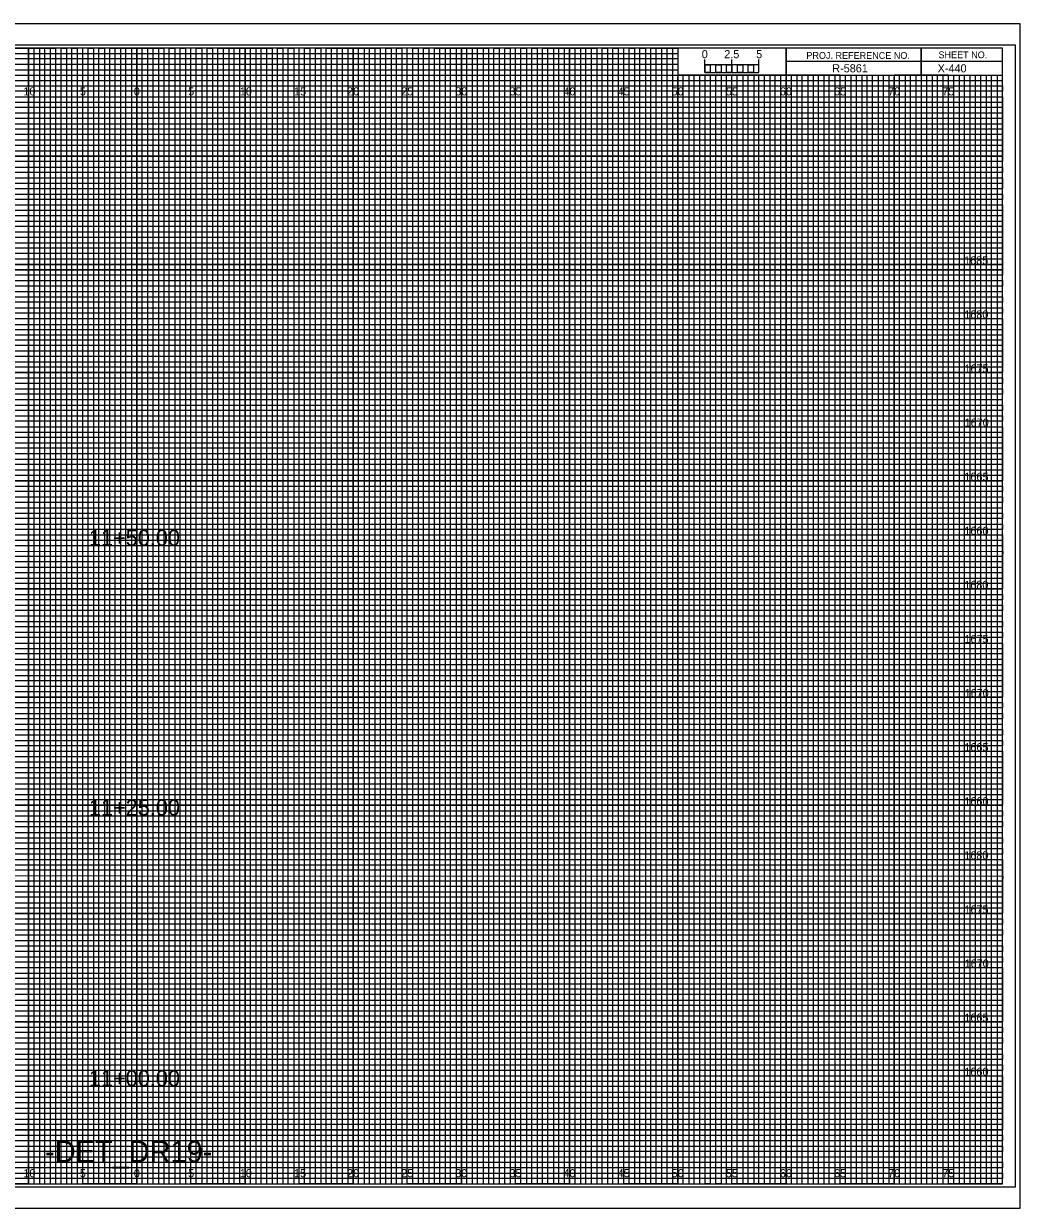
# Model space of a CAD drawing. Extents: x -7 to 162, y -2 to 327.
# Drawn here: x 69.5 to 161.7, y 217.7 to 327.2 of the extents above; entities that cross this region are included whole.
import ezdxf

# ---------------------------------------------------------------- set-up
doc = ezdxf.new("R2010")
doc.units = 0
for name, color, linetype in [('Prop Horizontal Alignment', 7, 'Continuous'), ('Prop XS Alignment Label', 7, 'Continuous'), ('Prop XS Bar Scale Labels', 7, 'Continuous'), ('Prop XS Project Number', 7, 'Continuous'), ('Prop XS Sheet Number', 7, 'Continuous'), ('Raster_Level_0', 7, 'Continuous'), ('Scratch_Level_3', 7, 'Continuous'), ('Sheet Cross Section CELL', 7, 'Continuous'), ('Sheet Cross Section Grid Major CELL', 7, 'Continuous'), ('Sheet Cross Section Grid Middle CELL', 7, 'Continuous'), ('Sheet Cross Section Grid Minor 1 CELL', 7, 'Continuous'), ('Sheet Cross Section Grid Minor 2 CELL', 7, 'Continuous'), ('Sheet Cross Section Scale CELL', 7, 'Continuous'), ('Sheet Cutting Line CELL', 7, 'Continuous'), ('Sheet DOT Grid CELL', 7, 'Continuous'), ('Sheet Plot Border Inside CELL', 7, 'Continuous'), ('Sheet Plot Border Outside CELL', 7, 'Continuous')]:
    doc.layers.add(name, color=color, linetype=linetype)

msp = doc.modelspace()

# ---------------------------------------------------------------- linework, layer by layer
at = {"layer": 'Sheet Cross Section CELL'}
for p, q in [((152.5, 325), (152.5, 322.5)), ((152.5, 322.5), (152.5, 325)), ((160, 323.75), (140, 323.75)), ((140, 323.75), (140, 322.5)), ((140, 322.5), (160, 322.5))]:
    msp.add_line(p, q, dxfattribs=at)
for points in [[(160, 325), (0, 325), (0, 220), (160, 220)], [(140, 325), (130, 325), (130, 322.51), (140, 322.51)], [(160, 325), (140, 325), (140, 322.5), (160, 322.5)]]:
    msp.add_lwpolyline(points, close=True, dxfattribs=at)
at = {"layer": 'Sheet Cross Section Grid Major CELL'}
for p, q in [((75, 325), (70, 325)), ((70, 325), (70, 220)), ((75, 220), (75, 325)), ((85, 325), (80, 325)), ((80, 325), (80, 220)), ((85, 220), (85, 325)), ((95, 325), (90, 325)), ((90, 325), (90, 220)), ((95, 220), (95, 325)), ((105, 325), (100, 325)), ((100, 325), (100, 220)), ((105, 220), (105, 325)), ((115, 325), (110, 325)), ((110, 325), (110, 220)), ((115, 220), (115, 325)), ((125, 325), (120, 325)), ((120, 325), (120, 220)), ((125, 220), (125, 325)), ((130, 325), (130, 220)), ((135, 220), (135, 322.5)), ((145, 322.5), (140, 322.5)), ((140, 322.5), (140, 220)), ((145, 220), (145, 322.5)), ((155, 322.5), (150, 322.5)), ((150, 322.5), (150, 220)), ((155, 220), (155, 322.5)), ((70, 220), (65, 220)), ((80, 220), (75, 220)), ((90, 220), (85, 220)), ((100, 220), (95, 220)), ((110, 220), (105, 220)), ((120, 220), (115, 220)), ((130, 220), (125, 220)), ((140, 220), (135, 220)), ((150, 220), (145, 220)), ((160, 220), (155, 220)), ((160, 220), (160, 220))]:
    msp.add_line(p, q, dxfattribs=at)
for points in [[(0, 320), (160, 320), (160, 315), (0, 315)], [(0, 310), (160, 310), (160, 305), (0, 305)], [(0, 300), (160, 300), (160, 295), (0, 295)], [(0, 290), (160, 290), (160, 285), (0, 285)], [(0, 280), (160, 280), (160, 275), (0, 275)], [(0, 270), (160, 270), (160, 265), (0, 265)], [(0, 260), (160, 260), (160, 255), (0, 255)], [(0, 250), (160, 250), (160, 245), (0, 245)], [(0, 240), (160, 240), (160, 235), (0, 235)], [(0, 230), (160, 230), (160, 225), (0, 225)]]:
    msp.add_lwpolyline(points, dxfattribs=at)
at = {"layer": 'Sheet Cross Section Grid Middle CELL'}
for points in [[(67.5, 325), (72.5, 325), (72.5, 220), (77.5, 220), (77.5, 325), (82.5, 325), (82.5, 220), (87.5, 220), (87.5, 325), (92.5, 325), (92.5, 220), (97.5, 220), (97.5, 325), (102.5, 325), (102.5, 220), (107.5, 220), (107.5, 325), (112.5, 325), (112.5, 220), (117.5, 220), (117.5, 325), (122.5, 325), (122.5, 220), (127.5, 220), (127.5, 325), (129.97, 325), (130, 325), (130, 322.5), (132.5, 322.5), (132.5, 220), (137.5, 220), (137.5, 322.5), (142.5, 322.5), (142.5, 220), (147.5, 220), (147.5, 322.5), (152.5, 322.5), (152.5, 220), (157.5, 220), (157.5, 322.5)], [(0, 322.5), (137.5, 322.5)], [(0, 312.5), (160, 312.5), (160, 317.5), (0, 317.5)], [(0, 302.5), (160, 302.5), (160, 307.5), (0, 307.5)], [(0, 292.5), (160, 292.5), (160, 297.5), (0, 297.5)], [(0, 282.5), (160, 282.5), (160, 287.5), (0, 287.5)], [(0, 272.5), (160, 272.5), (160, 277.5), (0, 277.5)], [(0, 262.5), (160, 262.5), (160, 267.5), (0, 267.5)], [(0, 252.5), (160, 252.5), (160, 257.5), (0, 257.5)], [(0, 242.5), (160, 242.5), (160, 247.5), (0, 247.5)], [(0, 232.5), (160, 232.5), (160, 237.5), (0, 237.5)], [(0, 222.5), (160, 222.5), (160, 227.5), (0, 227.5)]]:
    msp.add_lwpolyline(points, dxfattribs=at)
at = {"layer": 'Sheet Cross Section Grid Minor 1 CELL'}
for p, q in [((0, 324.5), (130, 324.5)), ((130, 324.5), (130, 323.99)), ((130, 323.99), (0, 323.99)), ((0, 323.5), (130, 323.5)), ((130, 323.5), (130, 322.94)), ((130, 322.94), (0, 322.94)), ((0, 322), (160, 322))]:
    msp.add_line(p, q, dxfattribs=at)
for points in [[(0, 321.5), (135, 321.5), (160, 321.5), (160, 321), (0, 321)], [(0, 320.5), (160, 320.5), (160, 319.5), (0, 319.5)], [(0, 319), (160, 319), (160, 318.5), (0, 318.49)], [(0, 318), (160, 318), (160, 317), (0, 317)], [(0, 316.5), (160, 316.5), (160, 316), (0, 316)], [(0, 315.5), (160, 315.5), (160, 314.5), (0, 314.5)], [(0, 314), (160, 314), (160, 313.5), (0, 313.5)], [(0, 313), (160, 313), (160, 312), (0, 312)], [(0, 311.5), (160, 311.5), (160, 311), (0, 311)], [(0, 310.5), (160, 310.5), (160, 309.5), (0, 309.5)], [(0, 309), (160, 309), (160, 308.5), (0, 308.5)], [(0, 308), (160, 308), (160, 306.98), (160, 306.5), (160, 306), (0, 306)], [(0, 307), (160, 307), (160, 306.5), (0, 306.5)], [(0, 305.5), (160, 305.5), (160, 304.5), (0, 304.51)], [(0, 304.51), (160, 304.5), (160, 304), (0, 304)], [(0, 303.5), (160, 303.5), (160, 303), (0, 303)], [(0, 302), (160, 302), (160, 301.5), (0, 301.5)], [(0, 301), (160, 301), (160, 300.5), (0, 300.5)], [(-0.04, 299.44), (160, 299.44), (160, 298.94), (-0.04, 298.94)], [(0, 298.5), (160, 298.5), (160, 298), (0, 298)], [(0, 297), (160, 297), (160, 296.5), (0, 296.5)], [(0, 296), (160, 296), (160, 295.5), (0, 295.5)], [(0, 294.5), (160, 294.5), (160, 294), (0, 294)], [(0, 293.5), (160, 293.5), (160, 293), (0, 293)], [(0, 292), (160, 292), (160, 291.5), (0, 291.5)], [(0, 291), (160, 291), (160, 290.5), (0, 290.5)], [(0, 289.5), (160, 289.5), (160, 288.99), (0, 289)], [(0, 288.5), (160, 288.5), (160, 288), (0, 288)], [(0, 287), (160, 287), (160, 286.5), (0, 286.5)], [(0, 286), (160, 286), (160, 285.5), (0, 285.5)], [(0, 284.5), (160, 284.5), (160, 284), (0, 284)], [(0, 283.5), (160, 283.5), (160, 283), (0, 283)], [(0, 282), (160, 282), (160, 281.5), (0, 281.5)], [(0, 281), (160, 281), (160, 280.5), (0, 280.5)], [(0, 279.5), (160, 279.5), (160, 279), (0, 279)], [(0, 278.5), (160.03, 278.45), (160, 278), (0, 278)], [(0, 277), (160, 277), (160, 276.5), (0, 276.5)], [(0, 276), (160, 276), (160, 275.5), (0, 275.5)], [(0, 274.5), (160, 274.5), (160, 274), (0, 274)], [(0, 273.5), (160, 273.5), (160, 273), (0, 273)], [(0, 272), (160, 272), (160, 271.5), (0, 271.5)], [(0, 271), (160, 271), (160, 270.5), (0, 270.5)], [(0, 269.5), (160, 269.5), (160, 269), (0, 269)], [(0, 268.5), (160, 268.5), (160, 268), (0, 268)], [(0, 267), (160, 267), (160, 266.5), (0, 266.5)], [(0, 266), (160, 266), (160, 265.5), (0, 265.5)], [(0, 264.5), (160, 264.5), (160, 264), (0, 264)], [(0, 263.5), (160, 263.5), (160, 263), (0, 263)], [(0, 262), (160, 262), (160, 261.5), (0, 261.5)], [(0, 261), (160, 261), (160, 260.5), (0, 260.5)], [(0, 259.5), (160, 259.5), (160, 258.99), (0, 259)], [(0, 258.5), (160, 258.5), (160, 258), (0, 258)], [(0, 257), (160, 257), (160, 256.5), (0, 256.5)], [(0, 256), (160, 256), (160, 255.5), (0, 255.5)], [(0, 254.5), (160, 254.5), (160, 254), (0, 254)], [(0, 253.5), (160, 253.5), (160, 253), (0, 253)], [(0, 252), (160, 252), (160, 251.5), (0, 251.5)], [(0, 251), (160, 251), (160, 250.5), (0, 250.5)], [(0, 249.5), (160, 249.5), (160, 249), (0, 249)], [(0, 248.5), (160.03, 248.46), (160, 248), (0, 248)], [(0, 247), (160, 247), (160, 246.5), (0, 246.5)], [(0, 246), (160, 246), (160, 245.5), (0, 245.5)], [(0, 244.5), (160, 244.5), (160, 244), (0, 244)], [(0, 243.5), (160, 243.5), (160, 243), (0, 243)], [(0, 242), (160, 242), (160, 241.5), (0, 241.5)], [(0, 241), (160, 241), (160, 240.5), (0, 240.5)], [(0, 239.5), (160, 239.5), (160, 239), (0, 239)], [(0, 238.5), (160, 238.5), (160, 238), (0, 238)], [(0, 237), (160, 237), (160, 236.5), (0, 236.5)], [(0, 236), (160, 236), (160, 235.5), (0, 235.5)], [(0, 234.5), (160, 234.5), (160, 234), (0, 234)], [(0, 233.5), (160, 233.5), (160, 233), (0, 233)], [(0, 232), (160, 232), (160, 231.5), (0, 231.5)], [(0, 231), (160, 231), (160, 230.5), (0, 230.5)], [(0, 229.5), (160, 229.5), (160, 229), (0, 229)], [(0, 228.5), (160, 228.5), (160, 228), (0, 228)], [(0, 227), (160, 227), (160, 226.5), (0, 226.5)], [(0, 226), (160, 226), (160, 225.5), (0, 225.5)], [(0, 224.5), (160, 224.5), (160, 224), (0, 224)], [(0, 223.5), (160, 223.5), (160, 223), (0, 223)], [(0, 222), (160, 222), (160, 221.5), (0, 221.5)], [(0, 221), (160, 221), (160, 220.5), (0, 220.5)]]:
    msp.add_lwpolyline(points, dxfattribs=at)
at = {"layer": 'Sheet Cross Section Grid Minor 2 CELL'}
for p, q in [((133.5, 322.5), (133, 322.5)), ((133, 322.5), (133, 220)), ((133.5, 220), (133.5, 322.5)), ((134.5, 322.5), (134, 322.5)), ((134, 322.5), (134, 220)), ((134.5, 220), (134.5, 322.5)), ((133, 220), (132.5, 220)), ((134, 220), (133.5, 220))]:
    msp.add_line(p, q, dxfattribs=at)
for points in [[(70, 220), (70.5, 220), (70.5, 325), (71, 325), (71, 220)], [(71, 220), (71.5, 220), (71.5, 325), (72, 325), (72, 220)], [(72.5, 220), (73, 220), (73, 325), (73.5, 325), (73.5, 220)], [(73.5, 220), (74, 220), (74, 325), (74.5, 325), (74.5, 220)], [(75, 220), (75.5, 220), (75.5, 325), (76, 325), (76, 220)], [(76, 220), (76.5, 220), (76.5, 325), (77, 325), (77, 220)], [(77.5, 220), (78, 220), (78, 325), (78.5, 325), (78.5, 220)], [(78.5, 220), (79, 220), (79, 325), (79.5, 325), (79.5, 220)], [(80, 220), (80.5, 220), (80.5, 325), (81, 325), (81, 220)], [(81, 220), (81.5, 220), (81.5, 325), (82, 325), (82, 220)], [(82.5, 220), (83, 220), (83, 325), (83.5, 325), (83.5, 220)], [(83.5, 220), (84, 220), (84, 325), (84.5, 325), (84.5, 220)], [(85, 220), (85.5, 220), (85.5, 325), (86, 325), (86, 220)], [(86, 220), (86.5, 220), (86.5, 325), (87, 325), (87, 220)], [(87.5, 220), (88, 220), (88, 325), (88.5, 325), (88.5, 220)], [(88.5, 220), (89, 220), (89, 325), (89.5, 325), (89.5, 220)], [(90, 220), (90.5, 220), (90.5, 325), (91, 325), (91, 220)], [(91, 220), (91.5, 220), (91.5, 325), (92, 325), (92, 220)], [(92.5, 220), (93, 220), (93, 325), (93.5, 325), (93.5, 220)], [(93.5, 220), (94, 220), (94, 325), (94.5, 325), (94.5, 220)], [(95, 220), (95.5, 220), (95.5, 325), (96, 325), (96, 220)], [(96, 220), (96.5, 220), (96.5, 325), (97, 325), (97, 220)], [(97.5, 220), (98, 220), (98, 325), (98.5, 325), (98.5, 220)], [(98.5, 220), (99, 220), (99, 325), (99.5, 325), (99.5, 220)], [(100, 220), (100.5, 220), (100.5, 325), (101, 325), (101, 220)], [(101, 220), (101.5, 220), (101.5, 325), (102, 325), (102, 220)], [(102.5, 220), (103, 220), (103, 325), (103.5, 325), (103.5, 220)], [(103.5, 220), (104, 220), (104, 325), (104.5, 325), (104.5, 220)], [(105, 220), (105.5, 220), (105.5, 325), (106, 325), (106, 220)], [(106, 220), (106.5, 220), (106.5, 325), (107, 325), (107, 220)], [(107.5, 220), (108, 220), (108, 325), (108.5, 325), (108.5, 220)], [(108.5, 220), (109, 220), (109, 325), (109.5, 325), (109.5, 220)], [(110, 220), (110.5, 220), (110.5, 325), (111, 325), (111, 220)], [(111, 220), (111.5, 220), (111.5, 325), (112, 325), (112, 220)], [(112.5, 220), (113, 220), (113, 325), (113.5, 325), (113.5, 220)], [(113.5, 220), (114, 220), (114, 325), (114.5, 325), (114.5, 220)], [(115, 220), (115.5, 220), (115.5, 325), (116, 325), (116, 220)], [(116, 220), (116.5, 220), (116.5, 325), (117, 325), (117, 220)], [(117.5, 220), (118, 220), (118, 325), (118.5, 325), (118.5, 220)], [(118.5, 220), (119, 220), (119, 325), (119.5, 325), (119.5, 220)], [(120, 220), (120.5, 220), (120.5, 325), (121, 325), (121, 220)], [(121, 220), (121.5, 220), (121.5, 325), (122, 325), (122, 220)], [(122.5, 220), (123, 220), (123, 325), (123.5, 325), (123.5, 220)], [(123.5, 220), (124, 220), (124, 325), (124.5, 325), (124.5, 220)], [(125, 220), (125.5, 220), (125.5, 325), (126, 325), (126, 220)], [(126, 220), (126.5, 220), (126.5, 325), (127, 325), (127, 220)], [(127.5, 220), (128, 220), (128, 325), (128.5, 325), (128.5, 220)], [(128.5, 220), (129, 220), (129, 325), (129.5, 325), (129.5, 220)], [(130, 220), (130.5, 220), (130.5, 322.5), (131.01, 322.5), (131.01, 220)], [(131, 220), (131.5, 220), (131.5, 322.5), (132, 322.5), (132, 220)], [(135, 220), (135.49, 220), (135.49, 322.5), (136, 322.5), (136, 220)], [(136, 220), (136.5, 220), (136.5, 322.5), (137.03, 322.5), (137.03, 220)], [(137.5, 220), (138, 220), (138, 322.5), (138.5, 322.5), (138.5, 220)], [(138.5, 220), (139, 220), (139, 322.5), (139.5, 322.5), (139.5, 220)], [(140, 220), (140.5, 220), (140.5, 322.5), (141, 322.5), (141, 220)], [(141, 220), (141.5, 220), (141.5, 322.5), (142, 322.5), (142, 220)], [(142.5, 220), (143, 220), (143, 322.5), (143.5, 322.5), (143.5, 220)], [(143.5, 220), (144, 220), (144, 322.5), (144.5, 322.5), (144.5, 220)], [(145, 220), (145.5, 220), (145.5, 322.5), (146, 322.5), (146, 220)], [(146, 220), (146.5, 220), (146.5, 322.5), (147, 322.5), (147, 220)], [(147.5, 220), (148, 220), (148, 322.5), (148.5, 322.5), (148.5, 220)], [(148.5, 220), (149, 220), (149, 322.5), (149.5, 322.5), (149.5, 220)], [(150, 220), (150.5, 220), (150.5, 322.5), (151, 322.5), (151, 220)], [(151, 220), (151.5, 220), (151.5, 322.5), (152, 322.5), (152, 220)], [(152.5, 220), (153, 220), (153, 322.5), (153.5, 322.5), (153.5, 220)], [(153.5, 220), (154, 220), (154, 322.5), (154.5, 322.5), (154.5, 220)], [(155, 220), (155.5, 220), (155.5, 322.5), (156, 322.5), (156, 220)], [(156, 220), (156.5, 220), (156.5, 322.5), (157, 322.5), (157, 220)], [(157.5, 220), (158, 220), (158, 322.5), (158.5, 322.5), (158.5, 220)], [(158.5, 220), (159, 220), (159, 322.5), (159.5, 322.5), (159.5, 220)]]:
    msp.add_lwpolyline(points, dxfattribs=at)
at = {"layer": 'Sheet Cross Section Scale CELL'}
for p, q in [((132.5, 322.75), (132.5, 323.95)), ((132.5, 323.45), (132.5, 323.95)), ((135, 322.75), (135, 323.95)), ((137.5, 322.75), (137.5, 323.95)), ((137.5, 323.45), (137.5, 323.95))]:
    msp.add_line(p, q, dxfattribs=at)
for points in [[(137.5, 323.45), (132.5, 323.45), (132.5, 322.75), (137.5, 322.75)], [(132.5, 323.45), (133, 323.45), (133, 322.75), (132.5, 322.75)], [(133.5, 323.45), (134, 323.45), (134, 322.75), (133.5, 322.75)], [(134.5, 323.45), (135, 323.45), (135, 322.75), (134.5, 322.75)], [(135.5, 323.45), (136, 323.45), (136, 322.75), (135.5, 322.75)], [(136.5, 323.45), (137, 323.45), (137, 322.75), (136.5, 322.75)]]:
    msp.add_lwpolyline(points, close=True, dxfattribs=at)
at = {"layer": 'Sheet Cutting Line CELL'}
for p, q in [((161.65, 327.25), (-6.7, 327.25)), ((-6.7, 217.75), (161.65, 217.75))]:
    msp.add_line(p, q, dxfattribs=at)
at = {"layer": 'Sheet DOT Grid CELL'}
for p, q in [((70, 220), (70, 325)), ((75, 220), (75, 325)), ((80, 220), (80, 325)), ((85, 220), (85, 325)), ((90, 220), (90, 325)), ((95, 220), (95, 325)), ((100, 220), (100, 325)), ((105, 220), (105, 325)), ((110, 220), (110, 325)), ((115, 220), (115, 325)), ((120, 220), (120, 325)), ((125, 220), (125, 325)), ((130, 220), (130, 322.34)), ((135, 220), (135, 322.34)), ((140, 220), (140, 322.34)), ((145, 220), (145, 322.34)), ((150, 220), (150, 322.34)), ((155, 220), (155, 322.34)), ((0, 320), (160, 320)), ((0, 315), (160, 315)), ((0, 310), (160, 310)), ((0, 305), (160, 305)), ((0, 300), (160, 300)), ((0, 295), (160, 295)), ((0, 290), (160, 290)), ((0, 285), (160, 285)), ((0, 280), (160, 280)), ((0, 275), (160, 275)), ((0, 270), (160, 270)), ((0, 265), (160, 265)), ((0, 260), (160, 260)), ((0, 255), (160, 255)), ((0, 250), (160, 250)), ((0, 245), (160, 245)), ((0, 240), (160, 240)), ((0, 235), (160, 235)), ((0, 230), (160, 230)), ((0, 225), (160, 225))]:
    msp.add_line(p, q, dxfattribs=at)
at = {"layer": 'Sheet Plot Border Inside CELL'}
msp.add_lwpolyline([(-5.4, 219.75), (161.2, 219.75), (161.2, 325.25), (-5.4, 325.25)], close=True, dxfattribs=at)
at = {"layer": 'Sheet Plot Border Outside CELL'}
msp.add_lwpolyline([(-6.7, 217.75), (161.65, 217.75), (161.65, 327.25), (-6.7, 327.25)], close=True, dxfattribs=at)

# ---------------------------------------------------------------- texts
at = {"layer": 'Prop Horizontal Alignment'}
for s, p in [('11+50.00', (75.57, 278.98)), ('11+25.00', (75.57, 254.05)), ('11+00.00', (75.57, 229.02))]:
    msp.add_text(s, height=1.5, dxfattribs=at).set_placement(p)
at = {"layer": 'Prop XS Alignment Label'}
msp.add_text('-DET_DR19-', height=2, dxfattribs=at).set_placement((71.53, 222))
at = {"layer": 'Prop XS Bar Scale Labels'}
for s, p in [('2.5', (134.29, 324.06)), ('5', (137.24, 324.06))]:
    msp.add_text(s, height=0.75, dxfattribs=at).set_placement(p)
at = {"layer": 'Prop XS Project Number'}
msp.add_text('R-5861', height=0.75, dxfattribs=at).set_placement((144.27, 322.75))
at = {"layer": 'Prop XS Sheet Number'}
msp.add_text('X-440', height=0.75, dxfattribs=at).set_placement((154.01, 322.75))
at = {"layer": 'Raster_Level_0'}
for s, p in [('10', (69.52, 320.62)), ('5', (74.74, 320.62)), ('0', (79.73, 320.62)), ('0', (79.73, 320.62)), ('5', (84.74, 320.62)), ('10', (89.52, 320.62)), ('15', (94.53, 320.62)), ('20', (99.43, 320.62)), ('25', (104.44, 320.62)), ('30', (109.43, 320.62)), ('35', (114.44, 320.62)), ('40', (119.43, 320.62)), ('45', (124.44, 320.62)), ('50', (129.43, 320.62)), ('55', (134.44, 320.62)), ('60', (139.43, 320.62)), ('65', (144.44, 320.62)), ('70', (149.43, 320.62)), ('75', (154.44, 320.62)), ('10', (69.52, 220.62)), ('5', (74.74, 220.62)), ('0', (79.73, 220.62)), ('0', (79.73, 220.62)), ('5', (84.74, 220.62)), ('10', (89.52, 220.62)), ('15', (94.53, 220.62)), ('20', (99.43, 220.62)), ('25', (104.44, 220.62)), ('30', (109.43, 220.62)), ('35', (114.44, 220.62)), ('40', (119.43, 220.62)), ('45', (124.44, 220.62)), ('50', (129.43, 220.62)), ('55', (134.44, 220.62)), ('60', (139.43, 220.62)), ('65', (144.44, 220.62)), ('70', (149.43, 220.62)), ('75', (154.44, 220.62))]:
    msp.add_text(s, height=0.75, dxfattribs=at).set_placement(p)
at = {"layer": 'Scratch_Level_3'}
for s, p in [('1685', (156.46, 305)), ('1680', (156.47, 300)), ('1675', (156.49, 295)), ('1670', (156.5, 290)), ('1665', (156.48, 285)), ('1660', (156.48, 280)), ('1680', (156.47, 275)), ('1675', (156.49, 270)), ('1670', (156.5, 265)), ('1665', (156.48, 260)), ('1660', (156.48, 255)), ('1680', (156.47, 250)), ('1675', (156.49, 245)), ('1670', (156.5, 240)), ('1665', (156.48, 235)), ('1660', (156.48, 230))]:
    msp.add_text(s, height=0.75, dxfattribs=at).set_placement(p)
at = {"layer": 'Sheet Cross Section CELL'}
for s, p in [('PROJ. REFERENCE NO.', (141.88, 324)), ('SHEET NO.', (154.09, 324.06))]:
    msp.add_text(s, height=0.625, dxfattribs=at).set_placement(p)
at = {"layer": 'Sheet Cross Section Scale CELL'}
msp.add_text('0', height=0.75, dxfattribs=at).set_placement((132.21, 324.06))

doc.saveas('drawing.dxf')
